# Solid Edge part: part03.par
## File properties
Author: Administrator
Template: normal.par
Last saved by: Rajat Kamboj
Revision: 17
Application: Solid Edge
Accuracy: 0.99
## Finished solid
Body 1: solid body, 54 faces, 136 edges, 72 vertices.
  Faces by surface: cylinder 40, plane 14
  Edges by curve: circle 74, line 50, ellipse 12
Bounding box of the edges (mm): 320.500 x 112.000 x 70.000, from (-118.4884, -56, -35) to (202.0116, 56, 35).
Cylindrical faces by radius (mm): R5 x8, R6 x2, R12 x1, R13 x8, R17.5 x1, R26 x1, R31.5 x3, R35 x2, R72.03 x8, R78 x4, R207.0766 x1, R207.2725 x1
Planar faces by outward normal: +y 1, +z 4, -y 1, -z 4, oblique 4
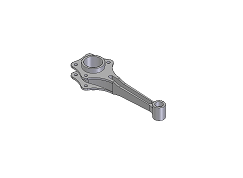
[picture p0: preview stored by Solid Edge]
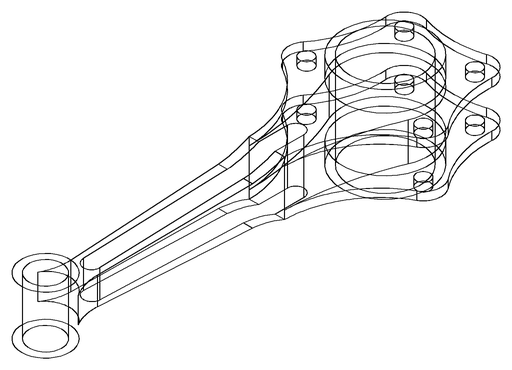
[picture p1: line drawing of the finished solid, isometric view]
